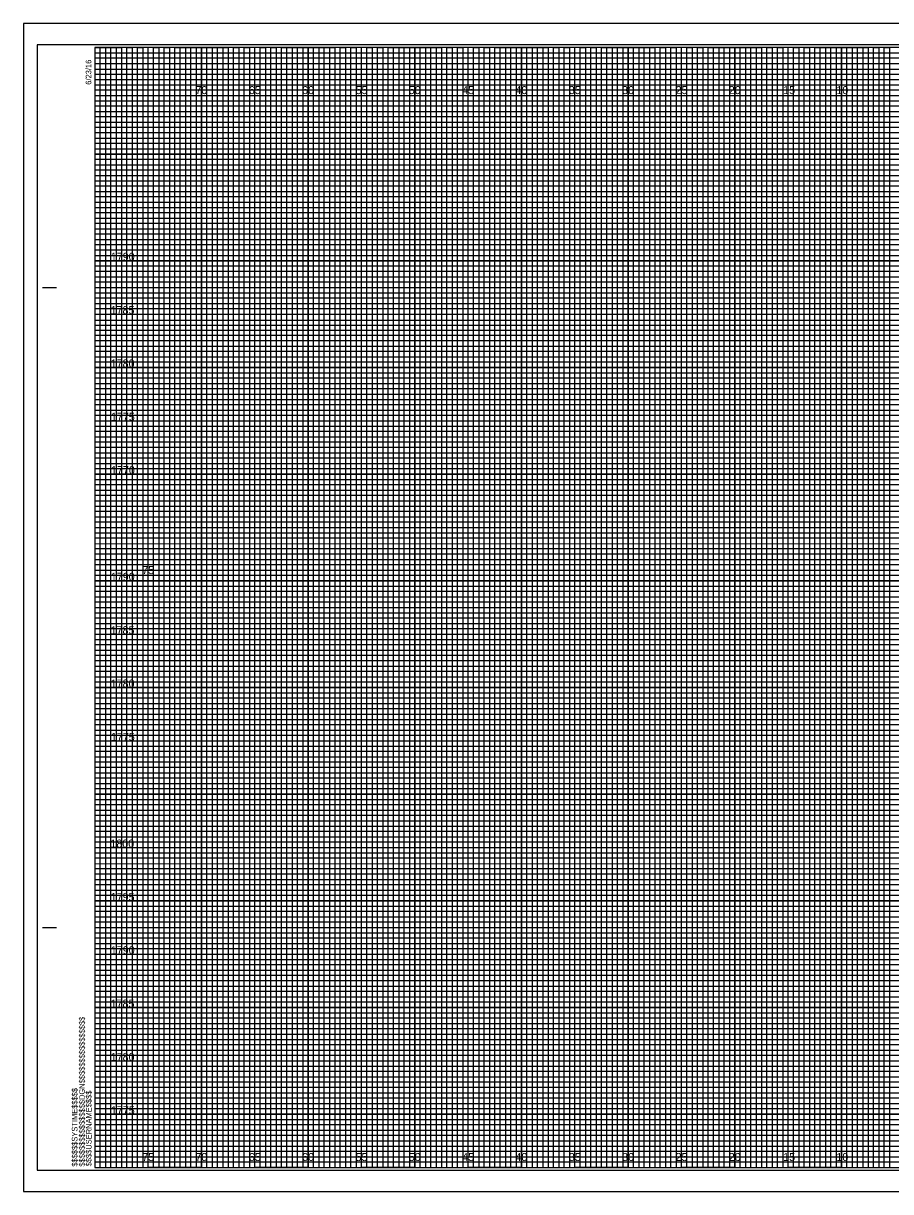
# Model space of a CAD drawing. Extents: x -7 to 162, y -2 to 327.
# Drawn here: x -6.7 to 74.6, y 217.7 to 327.2 of the extents above; entities that cross this region are included whole.
import ezdxf

# ---------------------------------------------------------------- set-up
doc = ezdxf.new("R2010")
doc.units = 0
for name, color, linetype in [('Raster_Level_0', 7, 'Continuous'), ('Scratch_Level_3', 7, 'Continuous'), ('Sheet Cross Section CELL', 7, 'Continuous'), ('Sheet Cross Section Grid Major CELL', 7, 'Continuous'), ('Sheet Cross Section Grid Middle CELL', 7, 'Continuous'), ('Sheet Cross Section Grid Minor 1 CELL', 7, 'Continuous'), ('Sheet Cross Section Grid Minor 2 CELL', 7, 'Continuous'), ('Sheet Cutting Line CELL', 7, 'Continuous'), ('Sheet DOT Grid CELL', 7, 'Continuous'), ('Sheet Plot Border Inside CELL', 7, 'Continuous'), ('Sheet Plot Border Outside CELL', 7, 'Continuous')]:
    doc.layers.add(name, color=color, linetype=linetype)

msp = doc.modelspace()

# ---------------------------------------------------------------- linework, layer by layer
at = {"layer": 'Sheet Cross Section CELL'}
for p, q in [((-4.9, 302.5), (-3.65, 302.5)), ((-4.85, 302.5), (-3.6, 302.5)), ((-4.9, 242.5), (-3.65, 242.5)), ((-4.85, 242.5), (-3.6, 242.5)), ((0, 220), (0, 220)), ((0, 220), (0, 220)), ((0, 220), (0, 220)), ((0, 220), (0, 220)), ((0, 220), (0, 220)), ((0, 220), (0, 220)), ((0, 220), (0, 220))]:
    msp.add_line(p, q, dxfattribs=at)
msp.add_lwpolyline([(160, 325), (0, 325), (0, 220), (160, 220)], close=True, dxfattribs=at)
at = {"layer": 'Sheet Cross Section Grid Major CELL'}
for p, q in [((5, 325), (0, 325)), ((5, 220), (5, 325)), ((15, 325), (10, 325)), ((10, 325), (10, 220)), ((15, 220), (15, 325)), ((25, 325), (20, 325)), ((20, 325), (20, 220)), ((25, 220), (25, 325)), ((35, 325), (30, 325)), ((30, 325), (30, 220)), ((35, 220), (35, 325)), ((45, 325), (40, 325)), ((40, 325), (40, 220)), ((45, 220), (45, 325)), ((55, 325), (50, 325)), ((50, 325), (50, 220)), ((55, 220), (55, 325)), ((65, 325), (60, 325)), ((60, 325), (60, 220)), ((65, 220), (65, 325)), ((75, 325), (70, 325)), ((70, 325), (70, 220)), ((10, 220), (5, 220)), ((20, 220), (15, 220)), ((30, 220), (25, 220)), ((40, 220), (35, 220)), ((50, 220), (45, 220)), ((60, 220), (55, 220)), ((70, 220), (65, 220))]:
    msp.add_line(p, q, dxfattribs=at)
for points in [[(0, 320), (160, 320), (160, 315), (0, 315)], [(0, 310), (160, 310), (160, 305), (0, 305)], [(0, 300), (160, 300), (160, 295), (0, 295)], [(0, 290), (160, 290), (160, 285), (0, 285)], [(0, 280), (160, 280), (160, 275), (0, 275)], [(0, 270), (160, 270), (160, 265), (0, 265)], [(0, 260), (160, 260), (160, 255), (0, 255)], [(0, 250), (160, 250), (160, 245), (0, 245)], [(0, 240), (160, 240), (160, 235), (0, 235)], [(0, 230), (160, 230), (160, 225), (0, 225)]]:
    msp.add_lwpolyline(points, dxfattribs=at)
at = {"layer": 'Sheet Cross Section Grid Middle CELL'}
for points in [[(0, 325), (2.5, 325), (2.5, 220), (7.5, 220), (7.5, 325), (12.5, 325), (12.5, 220), (17.5, 220), (17.5, 325), (22.5, 325), (22.5, 220), (27.5, 220), (27.5, 325), (32.5, 325), (32.5, 220), (37.5, 220), (37.5, 325), (42.5, 325), (42.5, 220), (47.5, 220), (47.5, 325), (52.5, 325), (52.5, 220), (57.5, 220), (57.5, 325), (62.5, 325), (62.5, 220), (67.5, 220), (67.5, 325), (72.5, 325), (72.5, 220), (77.5, 220)], [(0, 322.5), (137.5, 322.5)], [(0, 312.5), (160, 312.5), (160, 317.5), (0, 317.5)], [(0, 302.5), (160, 302.5), (160, 307.5), (0, 307.5)], [(0, 292.5), (160, 292.5), (160, 297.5), (0, 297.5)], [(0, 282.5), (160, 282.5), (160, 287.5), (0, 287.5)], [(0, 272.5), (160, 272.5), (160, 277.5), (0, 277.5)], [(0, 262.5), (160, 262.5), (160, 267.5), (0, 267.5)], [(0, 252.5), (160, 252.5), (160, 257.5), (0, 257.5)], [(0, 242.5), (160, 242.5), (160, 247.5), (0, 247.5)], [(0, 232.5), (160, 232.5), (160, 237.5), (0, 237.5)], [(0, 222.5), (160, 222.5), (160, 227.5), (0, 227.5)]]:
    msp.add_lwpolyline(points, dxfattribs=at)
at = {"layer": 'Sheet Cross Section Grid Minor 1 CELL'}
for p, q in [((0, 324.5), (130, 324.5)), ((130, 323.99), (0, 323.99)), ((0, 323.99), (0, 323.5)), ((0, 323.5), (130, 323.5)), ((130, 322.94), (0, 322.94)), ((0, 322.94), (0, 322)), ((0, 322), (160, 322))]:
    msp.add_line(p, q, dxfattribs=at)
for points in [[(0, 321.5), (135, 321.5), (160, 321.5), (160, 321), (0, 321)], [(0, 320.5), (160, 320.5), (160, 319.5), (0, 319.5)], [(0, 319), (160, 319), (160, 318.5), (0, 318.49)], [(0, 318), (160, 318), (160, 317), (0, 317)], [(0, 316.5), (160, 316.5), (160, 316), (0, 316)], [(0, 315.5), (160, 315.5), (160, 314.5), (0, 314.5)], [(0, 314), (160, 314), (160, 313.5), (0, 313.5)], [(0, 313), (160, 313), (160, 312), (0, 312)], [(0, 311.5), (160, 311.5), (160, 311), (0, 311)], [(0, 310.5), (160, 310.5), (160, 309.5), (0, 309.5)], [(0, 309), (160, 309), (160, 308.5), (0, 308.5)], [(0, 308), (160, 308), (160, 306.98), (160, 306.5), (160, 306), (0, 306)], [(0, 307), (160, 307), (160, 306.5), (0, 306.5)], [(0, 305.5), (160, 305.5), (160, 304.5), (0, 304.51)], [(0, 304.51), (160, 304.5), (160, 304), (0, 304)], [(0, 303.5), (160, 303.5), (160, 303), (0, 303)], [(0, 302), (160, 302), (160, 301.5), (0, 301.5)], [(0, 301), (160, 301), (160, 300.5), (0, 300.5)], [(-0.04, 299.44), (160, 299.44), (160, 298.94), (-0.04, 298.94)], [(0, 298.5), (160, 298.5), (160, 298), (0, 298)], [(0, 297), (160, 297), (160, 296.5), (0, 296.5)], [(0, 296), (160, 296), (160, 295.5), (0, 295.5)], [(0, 294.5), (160, 294.5), (160, 294), (0, 294)], [(0, 293.5), (160, 293.5), (160, 293), (0, 293)], [(0, 292), (160, 292), (160, 291.5), (0, 291.5)], [(0, 291), (160, 291), (160, 290.5), (0, 290.5)], [(0, 289.5), (160, 289.5), (160, 288.99), (0, 289)], [(0, 288.5), (160, 288.5), (160, 288), (0, 288)], [(0, 287), (160, 287), (160, 286.5), (0, 286.5)], [(0, 286), (160, 286), (160, 285.5), (0, 285.5)], [(0, 284.5), (160, 284.5), (160, 284), (0, 284)], [(0, 283.5), (160, 283.5), (160, 283), (0, 283)], [(0, 282), (160, 282), (160, 281.5), (0, 281.5)], [(0, 281), (160, 281), (160, 280.5), (0, 280.5)], [(0, 279.5), (160, 279.5), (160, 279), (0, 279)], [(0, 278.5), (160.03, 278.45), (160, 278), (0, 278)], [(0, 277), (160, 277), (160, 276.5), (0, 276.5)], [(0, 276), (160, 276), (160, 275.5), (0, 275.5)], [(0, 274.5), (160, 274.5), (160, 274), (0, 274)], [(0, 273.5), (160, 273.5), (160, 273), (0, 273)], [(0, 272), (160, 272), (160, 271.5), (0, 271.5)], [(0, 271), (160, 271), (160, 270.5), (0, 270.5)], [(0, 269.5), (160, 269.5), (160, 269), (0, 269)], [(0, 268.5), (160, 268.5), (160, 268), (0, 268)], [(0, 267), (160, 267), (160, 266.5), (0, 266.5)], [(0, 266), (160, 266), (160, 265.5), (0, 265.5)], [(0, 264.5), (160, 264.5), (160, 264), (0, 264)], [(0, 263.5), (160, 263.5), (160, 263), (0, 263)], [(0, 262), (160, 262), (160, 261.5), (0, 261.5)], [(0, 261), (160, 261), (160, 260.5), (0, 260.5)], [(0, 259.5), (160, 259.5), (160, 258.99), (0, 259)], [(0, 258.5), (160, 258.5), (160, 258), (0, 258)], [(0, 257), (160, 257), (160, 256.5), (0, 256.5)], [(0, 256), (160, 256), (160, 255.5), (0, 255.5)], [(0, 254.5), (160, 254.5), (160, 254), (0, 254)], [(0, 253.5), (160, 253.5), (160, 253), (0, 253)], [(0, 252), (160, 252), (160, 251.5), (0, 251.5)], [(0, 251), (160, 251), (160, 250.5), (0, 250.5)], [(0, 249.5), (160, 249.5), (160, 249), (0, 249)], [(0, 248.5), (160.03, 248.46), (160, 248), (0, 248)], [(0, 247), (160, 247), (160, 246.5), (0, 246.5)], [(0, 246), (160, 246), (160, 245.5), (0, 245.5)], [(0, 244.5), (160, 244.5), (160, 244), (0, 244)], [(0, 243.5), (160, 243.5), (160, 243), (0, 243)], [(0, 242), (160, 242), (160, 241.5), (0, 241.5)], [(0, 241), (160, 241), (160, 240.5), (0, 240.5)], [(0, 239.5), (160, 239.5), (160, 239), (0, 239)], [(0, 238.5), (160, 238.5), (160, 238), (0, 238)], [(0, 237), (160, 237), (160, 236.5), (0, 236.5)], [(0, 236), (160, 236), (160, 235.5), (0, 235.5)], [(0, 234.5), (160, 234.5), (160, 234), (0, 234)], [(0, 233.5), (160, 233.5), (160, 233), (0, 233)], [(0, 232), (160, 232), (160, 231.5), (0, 231.5)], [(0, 231), (160, 231), (160, 230.5), (0, 230.5)], [(0, 229.5), (160, 229.5), (160, 229), (0, 229)], [(0, 228.5), (160, 228.5), (160, 228), (0, 228)], [(0, 227), (160, 227), (160, 226.5), (0, 226.5)], [(0, 226), (160, 226), (160, 225.5), (0, 225.5)], [(0, 224.5), (160, 224.5), (160, 224), (0, 224)], [(0, 223.5), (160, 223.5), (160, 223), (0, 223)], [(0, 222), (160, 222), (160, 221.5), (0, 221.5)], [(0, 221), (160, 221), (160, 220.5), (0, 220.5)]]:
    msp.add_lwpolyline(points, dxfattribs=at)
at = {"layer": 'Sheet Cross Section Grid Minor 2 CELL'}
for points in [[(0, 220), (0.5, 220), (0.5, 325), (1, 325), (1, 220)], [(1, 220), (1.5, 220), (1.5, 325), (2, 325), (2, 220)], [(2.5, 220), (3, 220), (3, 325), (3.5, 325), (3.5, 220)], [(3.5, 220), (4, 220), (4, 325), (4.5, 325), (4.5, 220)], [(5, 220), (5.5, 220), (5.5, 325), (6, 325), (6, 220)], [(6, 220), (6.5, 220), (6.5, 325), (7, 325), (7, 220)], [(7.5, 220), (8, 220), (8, 325), (8.5, 325), (8.5, 220)], [(8.5, 220), (9, 220), (9, 325), (9.5, 325), (9.5, 220)], [(10, 220), (10.5, 220), (10.5, 325), (11, 325), (11, 220)], [(11, 220), (11.5, 220), (11.5, 325), (12, 325), (12, 220)], [(12.5, 220), (13, 220), (13, 325), (13.5, 325), (13.5, 220)], [(13.5, 220), (14, 220), (14, 325), (14.5, 325), (14.5, 220)], [(15, 220), (15.5, 220), (15.5, 325), (16, 325), (16, 220)], [(16, 220), (16.5, 220), (16.5, 325), (17, 325), (17, 220)], [(17.5, 220), (18, 220), (18, 325), (18.5, 325), (18.5, 220)], [(18.5, 220), (19, 220), (19, 325), (19.5, 325), (19.5, 220)], [(20, 220), (20.5, 220), (20.5, 325), (21, 325), (21, 220)], [(21, 220), (21.5, 220), (21.5, 325), (22, 325), (22, 220)], [(22.5, 220), (23, 220), (23, 325), (23.5, 325), (23.5, 220)], [(23.5, 220), (24, 220), (24, 325), (24.5, 325), (24.5, 220)], [(25, 220), (25.5, 220), (25.5, 325), (26, 325), (26, 220)], [(26, 220), (26.5, 220), (26.5, 325), (27, 325), (27, 220)], [(27.5, 220), (28, 220), (28, 325), (28.5, 325), (28.5, 220)], [(28.5, 220), (29, 220), (29, 325), (29.5, 325), (29.5, 220)], [(30, 220), (30.5, 220), (30.5, 325), (31, 325), (31, 220)], [(31, 220), (31.5, 220), (31.5, 325), (32, 325), (32, 220)], [(32.5, 220), (33, 220), (33, 325), (33.5, 325), (33.5, 220)], [(33.5, 220), (34, 220), (34, 325), (34.5, 325), (34.5, 220)], [(35, 220), (35.5, 220), (35.5, 325), (36, 325), (36, 220)], [(36, 220), (36.5, 220), (36.5, 325), (37, 325), (37, 220)], [(37.5, 220), (38, 220), (38, 325), (38.5, 325), (38.5, 220)], [(38.5, 220), (39, 220), (39, 325), (39.5, 325), (39.5, 220)], [(40, 220), (40.5, 220), (40.5, 325), (41, 325), (41, 220)], [(41, 220), (41.5, 220), (41.5, 325), (42, 325), (42, 220)], [(42.5, 220), (43, 220), (43, 325), (43.5, 325), (43.5, 220)], [(43.5, 220), (44, 220), (44, 325), (44.5, 325), (44.5, 220)], [(45, 220), (45.5, 220), (45.5, 325), (46, 325), (46, 220)], [(46, 220), (46.5, 220), (46.5, 325), (47, 325), (47, 220)], [(47.5, 220), (48, 220), (48, 325), (48.5, 325), (48.5, 220)], [(48.5, 220), (49, 220), (49, 325), (49.5, 325), (49.5, 220)], [(50, 220), (50.5, 220), (50.5, 325), (51, 325), (51, 220)], [(51, 220), (51.5, 220), (51.5, 325), (52, 325), (52, 220)], [(52.5, 220), (53, 220), (53, 325), (53.5, 325), (53.5, 220)], [(53.5, 220), (54, 220), (54, 325), (54.5, 325), (54.5, 220)], [(55, 220), (55.5, 220), (55.5, 325), (56, 325), (56, 220)], [(56, 220), (56.5, 220), (56.5, 325), (57, 325), (57, 220)], [(57.5, 220), (58, 220), (58, 325), (58.5, 325), (58.5, 220)], [(58.5, 220), (59, 220), (59, 325), (59.5, 325), (59.5, 220)], [(60, 220), (60.5, 220), (60.5, 325), (61, 325), (61, 220)], [(61, 220), (61.5, 220), (61.5, 325), (62, 325), (62, 220)], [(62.5, 220), (63, 220), (63, 325), (63.5, 325), (63.5, 220)], [(63.5, 220), (64, 220), (64, 325), (64.5, 325), (64.5, 220)], [(65, 220), (65.5, 220), (65.5, 325), (66, 325), (66, 220)], [(66, 220), (66.5, 220), (66.5, 325), (67, 325), (67, 220)], [(67.5, 220), (68, 220), (68, 325), (68.5, 325), (68.5, 220)], [(68.5, 220), (69, 220), (69, 325), (69.5, 325), (69.5, 220)], [(70, 220), (70.5, 220), (70.5, 325), (71, 325), (71, 220)], [(71, 220), (71.5, 220), (71.5, 325), (72, 325), (72, 220)], [(72.5, 220), (73, 220), (73, 325), (73.5, 325), (73.5, 220)], [(73.5, 220), (74, 220), (74, 325), (74.5, 325), (74.5, 220)]]:
    msp.add_lwpolyline(points, dxfattribs=at)
at = {"layer": 'Sheet Cutting Line CELL'}
for p, q in [((161.65, 327.25), (-6.7, 327.25)), ((-6.7, 327.25), (-6.7, 217.75)), ((-6.7, 217.75), (161.65, 217.75))]:
    msp.add_line(p, q, dxfattribs=at)
at = {"layer": 'Sheet DOT Grid CELL'}
for p, q in [((5, 220), (5, 325)), ((10, 220), (10, 325)), ((15, 220), (15, 325)), ((20, 220), (20, 325)), ((25, 220), (25, 325)), ((30, 220), (30, 325)), ((35, 220), (35, 325)), ((40, 220), (40, 325)), ((45, 220), (45, 325)), ((50, 220), (50, 325)), ((55, 220), (55, 325)), ((60, 220), (60, 325)), ((65, 220), (65, 325)), ((70, 220), (70, 325)), ((0, 320), (160, 320)), ((0, 315), (160, 315)), ((0, 310), (160, 310)), ((0, 305), (160, 305)), ((0, 300), (160, 300)), ((0, 295), (160, 295)), ((0, 290), (160, 290)), ((0, 285), (160, 285)), ((0, 280), (160, 280)), ((0, 275), (160, 275)), ((0, 270), (160, 270)), ((0, 265), (160, 265)), ((0, 260), (160, 260)), ((0, 255), (160, 255)), ((0, 250), (160, 250)), ((0, 245), (160, 245)), ((0, 240), (160, 240)), ((0, 235), (160, 235)), ((0, 230), (160, 230)), ((0, 225), (160, 225))]:
    msp.add_line(p, q, dxfattribs=at)
at = {"layer": 'Sheet Plot Border Inside CELL'}
msp.add_lwpolyline([(-5.4, 219.75), (161.2, 219.75), (161.2, 325.25), (-5.4, 325.25)], close=True, dxfattribs=at)
at = {"layer": 'Sheet Plot Border Outside CELL'}
msp.add_lwpolyline([(-6.7, 217.75), (161.65, 217.75), (161.65, 327.25), (-6.7, 327.25)], close=True, dxfattribs=at)

# ---------------------------------------------------------------- texts
at = {"layer": 'Raster_Level_0'}
for s, p in [('70', (9.43, 320.62)), ('65', (14.44, 320.62)), ('60', (19.43, 320.62)), ('55', (24.44, 320.62)), ('50', (29.43, 320.62)), ('45', (34.44, 320.62)), ('40', (39.43, 320.62)), ('35', (44.44, 320.62)), ('30', (49.43, 320.62)), ('25', (54.44, 320.62)), ('20', (59.43, 320.62)), ('15', (64.53, 320.62)), ('10', (69.52, 320.62)), ('75', (4.44, 275.63)), ('75', (4.44, 220.62)), ('70', (9.43, 220.62)), ('65', (14.44, 220.62)), ('60', (19.43, 220.62)), ('55', (24.44, 220.62)), ('50', (29.43, 220.62)), ('45', (34.44, 220.62)), ('40', (39.43, 220.62)), ('35', (44.44, 220.62)), ('30', (49.43, 220.62)), ('25', (54.44, 220.62)), ('20', (59.43, 220.62)), ('15', (64.53, 220.62)), ('10', (69.52, 220.62))]:
    msp.add_text(s, height=0.75, dxfattribs=at).set_placement(p)
at = {"layer": 'Scratch_Level_3'}
for s, p in [('1790', (1.5, 305)), ('1785', (1.48, 300)), ('1780', (1.49, 295)), ('1775', (1.51, 290)), ('1770', (1.52, 285)), ('1790', (1.5, 275)), ('1785', (1.48, 270)), ('1780', (1.49, 265)), ('1775', (1.51, 260)), ('1800', (1.46, 250)), ('1795', (1.49, 245)), ('1790', (1.5, 240)), ('1785', (1.48, 235)), ('1780', (1.49, 230)), ('1775', (1.51, 225))]:
    msp.add_text(s, height=0.75, dxfattribs=at).set_placement(p)
at = {"layer": 'Sheet Cross Section CELL'}
for s, p in [('6/23/16', (-0.33, 321.5)), ('$$$$$$$$$$$$$$$$DGN$$$$$$$$$$$$$$$$', (-0.94, 220.09)), ('$$$$$$SYSTIME$$$$$', (-1.63, 220.09)), ('$$$$USERNAME$$$$', (-0.31, 220.12))]:
    msp.add_text(s, height=0.525, rotation=90, dxfattribs=at).set_placement(p)

doc.saveas('drawing.dxf')
